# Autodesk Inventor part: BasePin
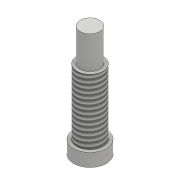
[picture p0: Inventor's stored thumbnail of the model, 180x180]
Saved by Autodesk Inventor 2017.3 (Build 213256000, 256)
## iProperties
Part Number: BasePin
Material: 一般
Document SubType Name: Modeling
Designer: kyushu-hep
Density: 1 g/cm^3
Appearance: 既定
Author: kyushu-hep
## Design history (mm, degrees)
sketch "スケッチ1"
  geometry: C1 r 2.5 at (0, 0); 1 further point
  constraints: 1 centre point, 1 coincident
  dimensions: "d0" = 5 diameter of C1
extrude "押し出し1" new body sketch "スケッチ1" distance "d1" = 2; taper "d2" = 0 deg
sketch "スケッチ2"
  geometry: C1 r 2 at (0, 0); 1 further point
  constraints: 1 centre point, 1 coincident
  dimensions: "d3" = 4 diameter of C1
extrude "押し出し2" join sketch "スケッチ2" distance "d4" = 10; taper "d5" = 0 deg
feature "ねじ1" dims "d6" = 10, "d7" = 0
sketch "スケッチ3"
  geometry: C1 r 1.5 at (0, 0); 1 further point
  constraints: 1 centre point, 1 coincident
  dimensions: "d8" = 3 diameter of C1
extrude "押し出し3" join sketch "スケッチ3" distance "d9" = 5; taper "d10" = 0 deg
node "ソリッド1"
